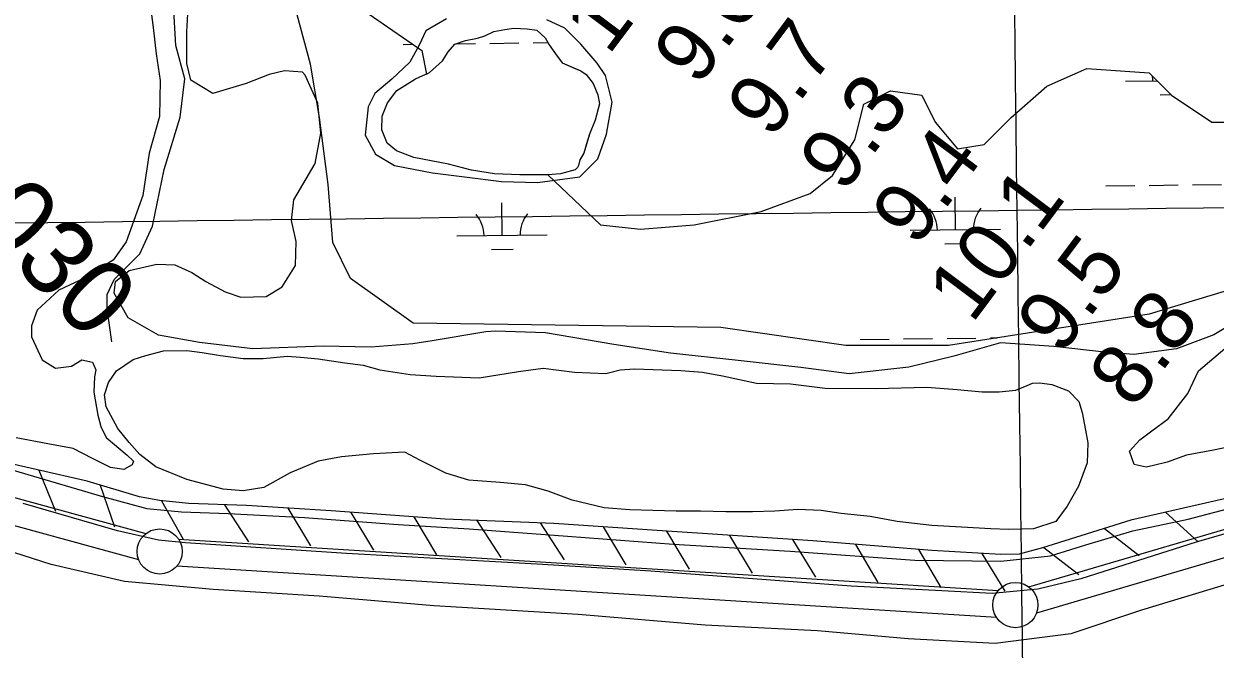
# Model space of a CAD drawing. Extents: x 3715084 to 3753216, y 488173 to 513963.
# Drawn here: x 3734024 to 3735343, y 499360 to 500052 of the extents above; entities that cross this region are included whole.
import ezdxf

# ---------------------------------------------------------------- set-up
doc = ezdxf.new("R2010")
doc.units = 0
for name, color, linetype in [('V-FLOD-BASE', 7, 'Continuous'), ('V-GRID-MAJR', 7, 'Continuous'), ('V-LEVE-TOET', 7, 'Continuous'), ('V-RIVR-RANG', 7, 'Continuous'), ('V-RIVR-RANG-IDEN', 7, 'Continuous'), ('V-ROAD-CNTR', 7, 'Continuous'), ('V-RRAP-FSHR', 7, 'Continuous'), ('V-SITE-VEGE', 7, 'Continuous'), ('V-SURV-IDEN', 7, 'Continuous'), ('V-SURV-LINE', 7, 'Continuous'), ('V-TOPO-SHOR', 7, 'Continuous'), ('V-WETL-SWMP', 7, 'Continuous')]:
    doc.layers.add(name, color=color, linetype=linetype)

msp = doc.modelspace()

# ---------------------------------------------------------------- linework, layer by layer
at = {"layer": 'V-FLOD-BASE'}
msp.add_lwpolyline([(3735448.1950000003, 499515.305), (3735321.761, 499478.689), (3735194.0640000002, 499438.282), (3735146.651, 499426.92100000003), (3735096.0840000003, 499421.88300000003), (3735040.46, 499425.064), (3734939.9590000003, 499430.157), (3734821.128, 499439.052), (3734718.099, 499446.672), (3734592.315, 499454.305), (3734381.201, 499466.393), (3734202.953, 499477.835), (3734173.247, 499481.005), (3734127.738, 499491.136), (3734023.454, 499521.514)], dxfattribs=at)
at = {"layer": 'V-GRID-MAJR'}
for points in [[(3735199.485, 493788.957), (3735123.717, 499845.93700000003), (3735047.9050000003, 505906.385), (3734972.094, 511966.84500000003), (3734972.051, 511970.3)], [(3719277.161, 499651.167), (3724559.356, 499715.322), (3729841.541, 499780.245), (3735123.717, 499845.93700000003), (3740405.883, 499912.396), (3745688.039, 499979.624), (3750970.185, 500047.621), (3750970.186, 500047.621)]]:
    msp.add_spline(points, degree=3, dxfattribs=at)
at = {"layer": 'V-LEVE-TOET'}
for points in [[(3734012.362, 499558.534), (3734111.0530000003, 499529.137), (3734160.4020000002, 499515.999), (3734198.507, 499512.237), (3734250.356, 499510.34500000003), (3734334.6890000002, 499505.941), (3734438.3850000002, 499498.407), (3734517.098, 499493.381), (3734625.791, 499485.22000000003), (3734743.2320000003, 499476.43200000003), (3734872.543, 499468.887), (3735010.598, 499458.842), (3735105.552, 499457.55700000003), (3735160.528, 499463.783), (3735199.889, 499475.639), (3735251.744, 499491.239), (3735312.969, 499504.33400000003), (3735363.575, 499517.435)], [(3735364.972, 499434.81), (3735261.261, 499403.613), (3735183.165, 499377.405), (3735099.451, 499366.815), (3735003.248, 499371.849), (3734902.6750000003, 499380.63), (3734778.361, 499386.924), (3734637.807, 499398.843), (3734478.514, 499408.272), (3734351.079, 499418.938), (3734233.636, 499426.479), (3734135.562, 499435.261), (3734054.358, 499454.031), (3733950.67, 499487.178)]]:
    msp.add_lwpolyline(points, dxfattribs=at)
at = {"layer": 'V-ROAD-CNTR'}
msp.add_spline([(3733715.5725298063, 498954.1440656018), (3733927.4081061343, 498985.4220030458), (3734149.04466286, 499017.4349390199), (3734317.1243267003, 499039.17989553), (3734452.533055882, 499051.021871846), (3734616.6037277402, 499062.12884963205), (3734803.4543540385, 499064.3688451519), (3734911.8351372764, 499064.8078442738), (3735132.1146967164, 499070.0368338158), (3735323.316314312, 499078.37181714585), (3735505.803949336, 499097.111779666), (3735898.0601648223, 499142.646688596), (3736237.231486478, 499184.4396050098), (3736547.3718661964, 499225.4965228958), (3736808.1873445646, 499257.56445876), (3736976.362008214, 499281.2394114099), (3737080.0268008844, 499296.4683809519), (3737176.0426088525, 499320.73933240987), (3737239.9724809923, 499343.32428724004), (3737319.351322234, 499377.88521811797), (3737388.8621832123, 499415.7931423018), (3737461.5770377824, 499455.86406216), (3737533.711893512, 499510.0739537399), (3737613.734733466, 499584.10580567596), (3737686.298588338, 499661.42465103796), (3737745.2314704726, 499744.2114854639), (3737793.210374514, 499828.8213162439), (3737831.048298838, 499907.621158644), (3737863.2922343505, 499993.6939864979), (3737884.48719196, 500070.0438337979), (3737902.013156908, 500150.4446729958), (3737918.8031233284, 500240.6464925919), (3737947.8120653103, 500405.0821637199), (3737975.5520098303, 500525.3699231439)], degree=3, dxfattribs=at)
at = {"layer": 'V-RRAP-FSHR'}
for p, q in [((3734040.735, 499558.406), (3734059.063, 499513.145)), ((3734108.727, 499541.84500000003), (3734124.324, 499495.572)), ((3734176.447, 499524.47500000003), (3734200.529, 499481.996)), ((3734246.281, 499520.091), (3734272.755, 499479.06)), ((3734316.1720000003, 499516.277), (3734341.589, 499474.583)), ((3734386.02, 499511.67), (3734411.1070000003, 499469.777)), ((3734455.842, 499506.684), (3734480.929, 499464.79000000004)), ((3735287.883, 499511.778), (3735324.165, 499479.096)), ((3734525.7260000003, 499502.825), (3734552.15, 499461.762)), ((3734595.673, 499500.091), (3734622.097, 499459.027)), ((3734665.5270000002, 499495.662), (3734690.67, 499453.802)), ((3734735.359, 499490.813), (3734760.683, 499449.06200000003)), ((3735220.2770000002, 499493.81700000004), (3735258.9050000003, 499463.945)), ((3734805.208, 499486.222), (3734830.532, 499444.471)), ((3734875.057, 499481.631), (3734900.381, 499439.88)), ((3734944.8510000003, 499476.283), (3734969.504, 499434.132)), ((3735014.6180000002, 499470.575), (3735039.271, 499428.425)), ((3735084.478, 499466.21), (3735110.151, 499424.674)), ((3735153.438, 499473.018), (3735192.066, 499443.147))]:
    msp.add_line(p, q, dxfattribs=at)
msp.add_lwpolyline([(3735353.1750000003, 499526.837), (3735249.6780000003, 499502.966), (3735151.9590000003, 499472.558), (3735126.042, 499465.565), (3735105.6520000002, 499464.99700000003), (3735029.362, 499469.369), (3734897.543, 499480.153), (3734725.058, 499491.49), (3734610.755, 499499.501), (3734490.691, 499504.195), (3734364.293, 499513.222), (3734270.577, 499519.17100000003), (3734206.694, 499521.59), (3734174.25, 499524.685), (3734152.288, 499529.047), (3734094.279, 499546.08900000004), (3733983.9620000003, 499571.466), (3733806.659, 499621.385), (3733663.9390000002, 499662.119)], dxfattribs=at)
at = {"layer": 'V-SITE-VEGE'}
for points in [[(3734163.5500000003, 500076.50800000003), (3734167.33, 500048.061), (3734170.48, 500018.984), (3734174.896, 499989.272), (3734174.248, 499949.44800000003), (3734162.855, 499908.996), (3734155.884, 499862.224), (3734137.536, 499811.028), (3734122.989, 499790.806), (3734086.318, 499768.696), (3734062.9250000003, 499757.325), (3734038.896, 499735.211)], [(3735406.3030000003, 499746.792), (3735341.356, 499707.985), (3735299.975, 499692.721), (3735252.864, 499686.37200000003), (3735220.4, 499688.93), (3735164.3850000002, 499695.318), (3735105.181, 499699.158), (3735053.615, 499684.53500000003), (3735003.957, 499672.458), (3734937.751, 499664.844), (3734884.2800000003, 499671.86600000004), (3734814.896, 499679.53), (3734739.781, 499687.835), (3734677.401, 499697.405), (3734601.6520000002, 499710.164), (3734546.272, 499712.093), (3734535.448, 499711.462), (3734476.242, 499701.298), (3734454.597, 499698.124), (3734408.7630000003, 499694.321), (3734355.292, 499695.613), (3734277.627, 499692.45900000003), (3734218.4280000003, 499699.48600000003), (3734173.233, 499707.776), (3734139.504, 499726.886), (3734124.236, 499754.266), (3734125.512, 499766.994), (3734140.794, 499779.083), (3734171.353, 499786.075), (3734191.085, 499785.43200000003), (3734210.181, 499777.15), (3734225.455, 499766.957), (3734247.094, 499755.49), (3734264.281, 499749.756), (3734292.289, 499750.38300000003), (3734310.119, 499761.196), (3734324.768, 499784.746), (3734325.413, 499811.483), (3734320.33, 499834.4), (3734322.884, 499857.31700000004), (3734346.452, 499897.413), (3734352.832, 499931.14900000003), (3734349.66, 499964.251), (3734335.668, 499995.44800000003), (3734332.485, 499998.635), (3734312.751, 499999.91500000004), (3734295.562, 499996.102), (3734270.095, 499985.925), (3734233.167, 499975.114), (3734208.987, 499989.767), (3734204.536, 500008.23), (3734204.549, 500043.24), (3734206.47, 500076.342)], [(3734492.153, 500057.759), (3734469.111, 500044.156), (3734461.775, 500028.452), (3734451.298, 500009.606), (3734431.395, 499990.767), (3734412.541, 499975.06700000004), (3734405.207, 499960.409), (3734402.056, 499928.999), (3734413.565, 499908.052), (3734434.502, 499895.477), (3734476.384, 499887.087), (3734511.984, 499882.884), (3734552.819, 499877.635), (3734592.608, 499876.572), (3734639.73, 499882.83900000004), (3734659.6350000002, 499902.72500000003), (3734669.068, 499929.947), (3734675.361, 499965.545), (3734668.042, 499994.869), (3734658.625, 500008.48600000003), (3734640.832, 500029.433), (3734623.037, 500047.238), (3734603.145, 500056.67100000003)], [(3734038.896, 499735.211), (3734032.707, 499718.204), (3734032.703, 499705.83400000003), (3734044.288, 499680.318), (3734058.975, 499671.037), (3734076.755, 499673.349), (3734088.353, 499680.302), (3734099.949, 499677.98), (3734103.812, 499669.474), (3734102.2630000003, 499661.743), (3734101.483, 499644.73600000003), (3734106.111, 499619.222), (3734109.2, 499606.853), (3734115.381, 499594.483), (3734138.566, 499575.145), (3734145.521, 499568.186), (3734143.973, 499564.322), (3734134.826, 499559.167), (3734120.169, 499561.264), (3734100.2770000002, 499571.221), (3734078.816, 499582.223), (3734050.545, 499587.47000000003), (3734015.471, 499594.288)]]:
    msp.add_lwpolyline(points, dxfattribs=at)
at = {"layer": 'V-SURV-LINE'}
for points in [[(3733340.159228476, 499712.4198921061), (3734159.1830544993, 499488.17734194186)], [(3734151.257310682, 499459.24323406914), (3733332.233517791, 499683.48577516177)], [(3735136.714858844, 499429.16287793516), (3735652.9176061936, 499580.7463425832)], [(3735661.385099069, 499551.96610970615), (3735145.1824448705, 499400.3826724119)], [(3734195.355103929, 499482.1589895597), (3735102.763086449, 499425.3624741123)], [(3735100.905729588, 499395.4200208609), (3734193.497439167, 499452.2165555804)]]:
    msp.add_lwpolyline(points, dxfattribs=at)
for centre in [(3734174.4835800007, 499468.43603), (3735121.77712, 499409.1431900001)]:
    msp.add_circle(centre, 25, dxfattribs=at)
at = {"layer": 'V-TOPO-SHOR'}
for points in [[(3734121.578, 499700.178), (3734116.464, 499737.347), (3734116.47, 499752.728), (3734124.167, 499769.386), (3734152.3740000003, 499797.57300000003), (3734166.4820000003, 499828.327), (3734179.323, 499891.123), (3734197.286, 499948.793), (3734202.429, 499991.08400000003), (3734192.1890000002, 500028.257), (3734189.643, 500073.117), (3734183.251, 500117.976), (3734147.387, 500178.228), (3734099.994, 500257.70900000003), (3734058.9990000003, 500310.273), (3734012.8740000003, 500348.739), (3733973.6410000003, 500373.804)], [(3734581.151, 500046.73), (3734592.145, 500045.155), (3734601.043, 500036.777), (3734605.752, 500028.92100000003), (3734612.5530000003, 500018.972), (3734619.881, 500009.02), (3734634.538, 500002.733), (3734640.8200000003, 500000.114), (3734646.577, 499995.92100000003), (3734654.427, 499985.972), (3734659.657, 499973.406), (3734661.224, 499963.456), (3734656.505, 499945.657), (3734650.218, 499929.95300000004), (3734647.072, 499919.484), (3734643.926, 499909.014), (3734639.736, 499901.685), (3734638.163, 499895.403), (3734637.115, 499893.31), (3734634.497, 499890.693), (3734618.265, 499885.987), (3734604.13, 499884.944), (3734573.24, 499884.957), (3734544.967, 499886.01300000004), (3734519.838, 499890.212), (3734494.187, 499897.028), (3734455.971, 499904.37200000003), (3734436.6010000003, 499911.708), (3734426.134, 499920.088), (3734420.379, 499934.75), (3734420.91, 499949.931), (3734426.6750000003, 499964.58900000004), (3734437.15, 499978.19800000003), (3734457.573, 499991.27900000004), (3734473.2830000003, 499998.08), (3734487.4220000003, 500011.163), (3734493.71, 500021.11), (3734501.042, 500029.484), (3734513.086, 500033.666), (3734526.1750000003, 500036.27900000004), (3734534.5530000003, 500038.895), (3734544.502, 500043.603), (3734556.544, 500045.694), (3734566.492, 500047.261), (3734581.151, 500046.73)], [(3735148.867, 499655.159), (3735162.14, 499653.256), (3735180.47, 499646.297), (3735191.842, 499634.281), (3735195.631, 499622.272), (3735199.418, 499602.675), (3735201.941, 499588.767), (3735201.3000000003, 499566.642), (3735191.809, 499540.729), (3735179.159, 499518.608), (3735166.511, 499501.54600000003), (3735141.855, 499493.338), (3735114.041, 499492.715), (3735094.446, 499493.356), (3735062.208, 499495.26300000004), (3735029.34, 499497.172), (3734990.782, 499501.612), (3734961.074, 499507.31200000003), (3734928.836, 499510.484), (3734906.714, 499513.652), (3734880.796, 499514.92600000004), (3734855.511, 499513.04000000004), (3734830.86, 499512.41500000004), (3734801.149, 499512.427), (3734773.338, 499513.068), (3734746.154, 499513.079), (3734720.239, 499513.72000000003), (3734694.954, 499514.363), (3734666.5100000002, 499516.9), (3734631.114, 499525.131), (3734604.568, 499535.254), (3734579.287, 499542.218), (3734551.4760000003, 499544.755), (3734516.7090000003, 499547.297), (3734491.426, 499554.893), (3734462.355, 499569.44200000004), (3734445.924, 499578.297), (3734411.157, 499576.413), (3734375.755, 499573.265), (3734349.838, 499568.217), (3734318.86, 499555.587), (3734289.776, 499539.162), (3734267.019, 499535.37700000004), (3734244.894, 499537.282), (3734204.4420000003, 499548.044), (3734170.3140000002, 499561.962), (3734152.619, 499575.87700000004), (3734140.614, 499589.156), (3734127.978, 499604.329), (3734115.344, 499628.355), (3734113.451, 499641.63), (3734117.881, 499655.536), (3734126.737, 499668.17600000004), (3734145.073, 499680.81), (3734158.981, 499685.23), (3734178.578, 499690.28), (3734204.495, 499690.902), (3734221.561, 499688.367), (3734241.787, 499685.201), (3734267.072, 499682.031), (3734289.196, 499682.022), (3734315.747, 499684.539), (3734330.2830000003, 499683.272), (3734349.879, 499681.367), (3734379.5870000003, 499676.931), (3734399.813, 499674.396), (3734418.143, 499669.333), (3734451.644, 499664.262), (3734480.719, 499662.355), (3734528.128, 499660.443), (3734571.747, 499667.379), (3734598.93, 499671.162), (3734633.6950000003, 499666.726), (3734668.4620000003, 499665.44800000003), (3734684.2660000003, 499669.235), (3734700.068, 499670.492), (3734751.268, 499668.577), (3734775.289, 499666.673), (3734797.412, 499662.87200000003), (3734835.3370000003, 499654.641), (3734872.631, 499653.995), (3734911.188, 499648.925), (3734967.447, 499648.902), (3735023.7060000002, 499650.147), (3735057.207, 499647.606), (3735085.019, 499645.068), (3735103.983, 499645.06), (3735122.315, 499646.95), (3735134.9590000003, 499652.003), (3735140.648, 499654.53), (3735148.867, 499655.159)], [(3735371.347, 499586.809), (3735341.002, 499580.499), (3735311.292, 499574.82), (3735289.796, 499567.242), (3735274.6240000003, 499563.455), (3735266.4080000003, 499561.561), (3735253.133, 499564.727), (3735248.082, 499579.268), (3735259.463, 499591.906), (3735272.742, 499602.015), (3735291.078, 499615.282), (3735312.58, 499643.088), (3735324.602, 499668.368), (3735353.687, 499693.01)]]:
    msp.add_lwpolyline(points, dxfattribs=at)
at = {"layer": 'V-WETL-SWMP'}
for p, q in [((3734444.052049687, 500029.28800061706), (3734454.8070490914, 500029.42240822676)), ((3734502.586278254, 500030.01951583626), (3734524.045803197, 500030.2877002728)), ((3734540.0445538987, 500030.48764020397), (3734572.0420553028, 500030.8875200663)), ((3734588.040806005, 500031.08745999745), (3734604.3311802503, 500031.29104441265)), ((3735243.8477298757, 499988.53726208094), (3735278.8394387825, 499988.97456121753)), ((3735282.0375923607, 499973.58232428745), (3735294.081164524, 499973.7328354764)), ((3735221.884024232, 499872.82176302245), (3735253.881525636, 499873.2216428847)), ((3735269.880276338, 499873.4215828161), (3735301.8777777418, 499873.8214626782)), ((3735317.876528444, 499874.0214026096), (3735349.8740298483, 499874.4212824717)), ((3735055.4132694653, 499824.3077155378), (3735054.96340462, 499860.30490461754)), ((3734553.544459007, 499818.0357498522), (3734553.094594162, 499854.03293893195)), ((3735005.417173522, 499823.68290325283), (3735105.409365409, 499824.9325278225)), ((3734503.548363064, 499817.41093756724), (3734603.540554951, 499818.6605621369)), ((3735043.607036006, 499808.72796545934), (3735067.605162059, 499809.0278753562)), ((3734541.738225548, 499802.45599977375), (3734565.736351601, 499802.7559096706)), ((3734950.0780486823, 499702.9109419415), (3734982.0755500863, 499703.3108218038)), ((3734998.074300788, 499703.51076173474), (3735030.071802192, 499703.9106415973)), ((3735046.0705528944, 499704.11058152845), (3735078.068054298, 499704.5104613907)), ((3735094.0668050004, 499704.7104013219), (3735101.5162070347, 499704.80349814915))]:
    msp.add_line(p, q, dxfattribs=at)
for points in [[(3735368.84, 499760.658), (3735270.044, 499731.01900000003), (3735047.751, 499696.44), (3734934.1350000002, 499696.44), (3734795.8200000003, 499716.199), (3734454.972, 499721.139), (3734385.8140000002, 499770.538), (3734366.055, 499810.056), (3734361.115, 499874.27400000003), (3734351.235, 499948.371), (3734341.356, 500007.64900000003), (3734326.536, 500061.988)], [(3734400.633, 500066.927), (3734464.8510000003, 500022.469), (3734469.791, 499996.569), (3734473.282, 499998.08), (3734487.423, 500011.163), (3734493.7090000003, 500021.109), (3734501.042, 500029.483), (3734513.085, 500033.667), (3734526.1750000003, 500036.28), (3734534.5530000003, 500038.89400000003), (3734544.502, 500043.603), (3734556.544, 500045.693), (3734566.492, 500047.26), (3734581.151, 500046.731), (3734592.145, 500045.156), (3734601.043, 500036.776), (3734605.752, 500028.92100000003), (3734612.554, 500018.971)], [(3734612.554, 500018.971), (3734619.88, 500009.021), (3734640.819, 500000.113), (3734646.577, 499995.922), (3734654.426, 499985.972), (3734659.657, 499973.405), (3734661.224, 499963.457), (3734656.506, 499945.658), (3734650.218, 499929.95300000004), (3734643.927, 499909.014), (3734639.736, 499901.685), (3734638.163, 499895.403), (3734637.115, 499893.31), (3734634.497, 499890.693), (3734618.265, 499885.987), (3734604.129, 499884.945), (3734604.078, 499884.945), (3734662.4450000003, 499829.816), (3734706.903, 499824.876)], [(3734706.903, 499824.876), (3734766.181, 499829.816), (3734840.278, 499844.635), (3734894.617, 499864.39400000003), (3734919.316, 499884.15400000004), (3734944.015, 499923.672), (3734953.895, 499963.191), (3734983.534, 499978.01), (3735018.112, 499973.071), (3735032.932, 499943.43200000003), (3735057.631, 499913.793), (3735087.27, 499918.732), (3735116.909, 499948.371), (3735156.4280000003, 499982.95), (3735200.886, 500002.71), (3735270.044, 499997.77), (3735294.7430000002, 499973.071), (3735339.201, 499943.43200000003), (3735378.72, 499943.43200000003)]]:
    msp.add_lwpolyline(points, dxfattribs=at)
for centre, radius, start, end in [((3735238.5992698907, 499988.94651117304), 35.24628790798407, 359.94418071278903, 8.886997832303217), ((3735000.1687135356, 499824.09215234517), 35.24628790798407, 359.94418071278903, 41.48783904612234), ((3735110.6459588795, 499825.4728109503), 35.246287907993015, 139.9441777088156, 181.48783604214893), ((3734498.299903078, 499817.8201866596), 35.24628790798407, 359.94418071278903, 41.48783904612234), ((3734608.7771484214, 499819.20084526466), 35.246287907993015, 139.9441777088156, 181.48783604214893)]:
    msp.add_arc(centre, radius, start, end, dxfattribs=at)

# ---------------------------------------------------------------- texts
at = {"layer": 'V-RIVR-RANG'}
for s, p in [('10.3', (3734671.382384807, 500016.17102405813)), ('9.6', (3734770.3971008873, 499981.5686778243)), ('9.7', (3734851.705731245, 499923.3167751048)), ('9.3', (3734931.9077312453, 499863.58677510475)), ('9.4', (3735012.1097312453, 499803.85677510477)), ('10.1', (3735073.815195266, 499719.4224348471)), ('9.5', (3735172.513731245, 499684.3977751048)), ('8.8', (3735252.715731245, 499624.66777510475))]:
    msp.add_text(s, height=66.99999999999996, rotation=53.17832571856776, dxfattribs=at).set_placement(p)
at = {"layer": 'V-RIVR-RANG-IDEN'}
msp.add_text('D-030', height=82.99999999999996, rotation=314.32532571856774, dxfattribs=at).set_placement((3733885.311768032, 499915.44816912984))
at = {"layer": 'V-SURV-IDEN'}
msp.add_text('590+05.2', height=99.99999999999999, rotation=329.2283745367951, dxfattribs=at).set_placement((3733512.3465164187, 499502.9109983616))

doc.saveas('drawing.dxf')
